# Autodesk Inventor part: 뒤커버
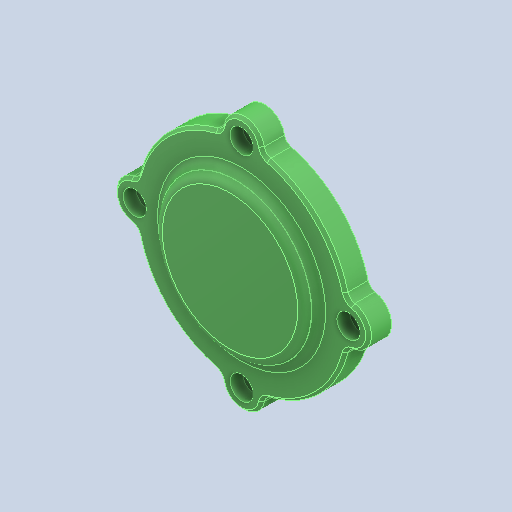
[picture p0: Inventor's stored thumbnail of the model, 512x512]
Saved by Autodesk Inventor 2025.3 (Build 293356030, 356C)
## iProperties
Created: 2025-08
Part Number: 뒤커버
Material: 알루미늄 6061
Document SubType Name: Modeling
Designer: user
Density: 2.71 g/cm^3
Appearance: 기본값
Company: 한국ATC센터
Sending System: Autodesk Inventor 2026
Preprocessor: ST-DEVELOPER v20.1
Author: jhkim
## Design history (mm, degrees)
sketch "스케치1"
  geometry: 1 further point
  constraints: 1 other
feature "솔리드1"
node "솔리드2"
